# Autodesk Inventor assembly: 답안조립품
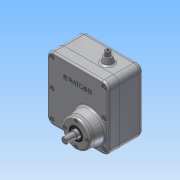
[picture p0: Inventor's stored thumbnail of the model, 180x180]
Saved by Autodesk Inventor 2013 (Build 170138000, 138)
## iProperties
Created: 2015-10
Part Number: 답안조립품
Document SubType Name: Assembly
Designer: Administrator
Mass: 1079.51 g
Surface Area: 1352.06 cm^2
Volume: 279.091 cm^3
Density: 3.86796 g/cm^3
Author: Administrator
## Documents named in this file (15)
- C:\Users\Administrator\Desktop\351008V1025\답안조립품.iam
- C:\Users\Administrator\Desktop\351008V1025\본체.ipt
- C:\Users\Administrator\Desktop\351008V1025\커버.ipt
- C:\Users\Administrator\Desktop\351008V1025\베어링 6002.ipt
- C:\Users\Administrator\Desktop\351008V1025\베어링 6001.ipt
- C:\Users\Administrator\Desktop\351008V1025\축 커버.ipt
- C:\Users\Administrator\Desktop\351008V1025\M3 x 0.5.ipt
- C:\Users\Administrator\Desktop\351008V1025\오일실 12 x 22.ipt
- C:\Users\Administrator\Desktop\351008V1025\로드 축.ipt
- C:\Users\Administrator\Desktop\351008V1025\로드.ipt
- C:\Users\Administrator\Desktop\351008V1025\편심 축.ipt
- C:\Users\Administrator\Desktop\351008V1025\M4 x 0.7.ipt
- C:\Users\Administrator\Desktop\351008V1025\오일실 15 x 25.ipt
- C:\Users\Administrator\Desktop\351008V1025\슬라이드.ipt
- C:\Users\Administrator\Desktop\351008V1025\가변 스프링.ipt
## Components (11 placed, 3 different names)
1. M4 x 0.7:1
2. M4 x 0.7:2
3. M4 x 0.7:3
4. M4 x 0.7:4
5. M4 x 0.7:5
6. M4 x 0.7:6
7. 가변 스프링:1
8. M3 x 0.5:1
9. M3 x 0.5:2
10. M3 x 0.5:3
11. M3 x 0.5:4
